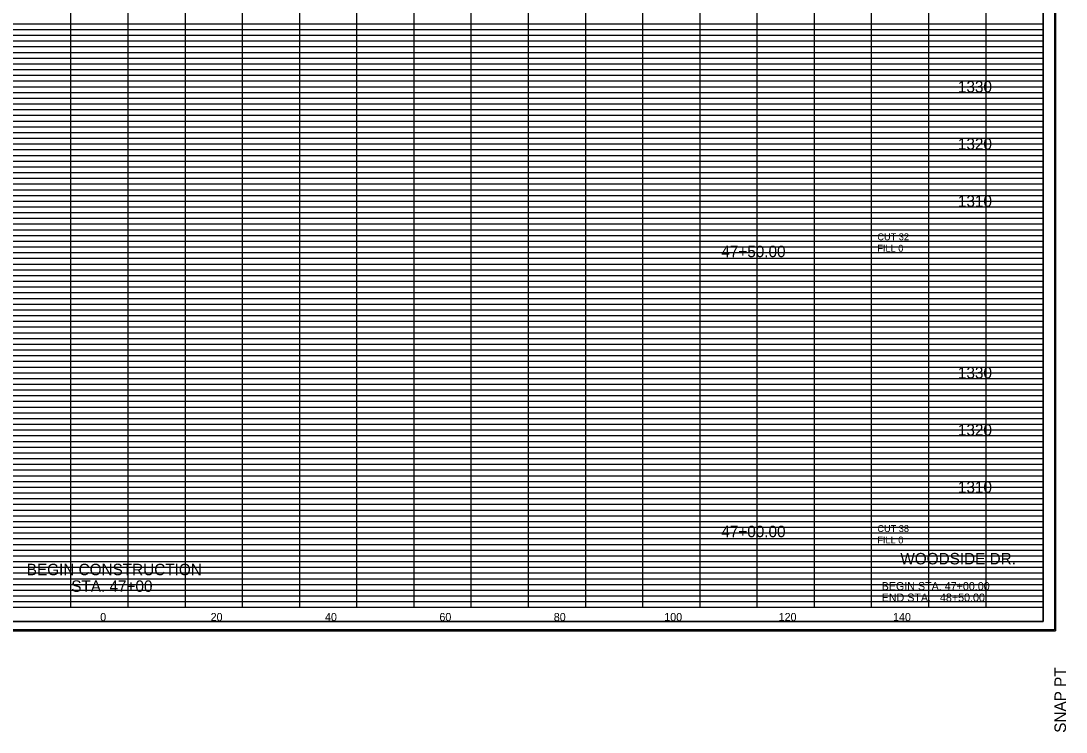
# Model space of a CAD drawing. Extents: x 980 to 1324, y 978 to 1497.
# Drawn here: x 1141.2 to 1324, y 978.2 to 1102.5 of the extents above; entities that cross this region are included whole.
import ezdxf

# ---------------------------------------------------------------- set-up
doc = ezdxf.new("R2010")
doc.units = 0
for name, color, linetype in [('DESIGN - SHEET - Corner Text', 7, 'Continuous'), ('DESIGN - SHEET - Light Grid', 7, 'Continuous'), ('DESIGN - SHEET - Linework', 7, 'Continuous'), ('DESIGN - SHEET - Plot Shape', 7, 'Continuous'), ('DESIGN - TYPICAL - Finished Grade and Subgrade', 7, 'Continuous'), ('DESIGN - TYPICAL - Text', 7, 'Continuous')]:
    doc.layers.add(name, color=color, linetype=linetype)

# ---------------------------------------------------------------- blocks, each defined once
blk = doc.blocks.new('XSTSHT')
at = {"layer": 'DESIGN - SHEET - Light Grid'}
for p, q in [((8, 10.2), (16, 10.2)), ((8, 10.1), (16, 10.1)), ((16, 10.2), (24, 10.2)), ((16, 10.1), (24, 10.1)), ((24, 10.2), (32, 10.2)), ((24, 10.1), (32, 10.1)), ((8, 9.9), (16, 9.9)), ((16, 9.9), (24, 9.9)), ((24, 9.9), (32, 9.9)), ((8, 9.8), (16, 9.8)), ((8, 9.7), (16, 9.7)), ((16, 9.8), (24, 9.8)), ((16, 9.7), (24, 9.7)), ((24, 9.8), (32, 9.8)), ((24, 9.7), (32, 9.7)), ((8, 9.6), (16, 9.6)), ((16, 9.6), (24, 9.6)), ((24, 9.6), (32, 9.6)), ((8, 9.5), (16, 9.5)), ((8, 9.4), (16, 9.4)), ((16, 9.5), (24, 9.5)), ((16, 9.4), (24, 9.4)), ((24, 9.5), (32, 9.5)), ((24, 9.4), (32, 9.4)), ((8, 9.3), (16, 9.3)), ((8, 9.2), (16, 9.2)), ((16, 9.3), (24, 9.3)), ((16, 9.2), (24, 9.2)), ((24, 9.3), (32, 9.3)), ((24, 9.2), (32, 9.2)), ((8, 9.1), (16, 9.1)), ((16, 9.1), (24, 9.1)), ((24, 9.1), (32, 9.1)), ((8, 8.9), (16, 8.9)), ((8, 8.8), (16, 8.8)), ((16, 8.9), (24, 8.9)), ((16, 8.8), (24, 8.8)), ((24, 8.9), (32, 8.9)), ((24, 8.8), (32, 8.8)), ((8, 8.7), (16, 8.7)), ((8, 8.6), (16, 8.6)), ((16, 8.7), (24, 8.7)), ((16, 8.6), (24, 8.6)), ((24, 8.7), (32, 8.7)), ((24, 8.6), (32, 8.6)), ((8, 8.5), (16, 8.5)), ((16, 8.5), (24, 8.5)), ((24, 8.5), (32, 8.5)), ((8, 8.4), (16, 8.4)), ((8, 8.3), (16, 8.3)), ((16, 8.4), (24, 8.4)), ((16, 8.3), (24, 8.3)), ((24, 8.4), (32, 8.4)), ((24, 8.3), (32, 8.3)), ((8, 8.2), (16, 8.2)), ((8, 8.1), (16, 8.1)), ((16, 8.2), (24, 8.2)), ((16, 8.1), (24, 8.1)), ((24, 8.2), (32, 8.2)), ((24, 8.1), (32, 8.1)), ((8, 7.9), (16, 7.9)), ((16, 7.9), (24, 7.9)), ((24, 7.9), (32, 7.9)), ((8, 7.8), (16, 7.8)), ((8, 7.7), (16, 7.7)), ((16, 7.8), (24, 7.8)), ((16, 7.7), (24, 7.7)), ((24, 7.8), (32, 7.8)), ((24, 7.7), (32, 7.7)), ((8, 7.6), (16, 7.6)), ((8, 7.5), (16, 7.5)), ((16, 7.6), (24, 7.6)), ((16, 7.5), (24, 7.5)), ((24, 7.6), (32, 7.6)), ((24, 7.5), (32, 7.5)), ((8, 7.4), (16, 7.4)), ((16, 7.4), (24, 7.4)), ((24, 7.4), (32, 7.4)), ((8, 7.3), (16, 7.3)), ((8, 7.2), (16, 7.2)), ((16, 7.3), (24, 7.3)), ((16, 7.2), (24, 7.2)), ((24, 7.3), (32, 7.3)), ((24, 7.2), (32, 7.2)), ((8, 7.1), (16, 7.1)), ((16, 7.1), (24, 7.1)), ((24, 7.1), (32, 7.1)), ((8, 6.9), (16, 6.9)), ((8, 6.8), (16, 6.8)), ((16, 6.9), (24, 6.9)), ((16, 6.8), (24, 6.8)), ((24, 6.9), (32, 6.9)), ((24, 6.8), (32, 6.8)), ((8, 6.7), (16, 6.7)), ((8, 6.6), (16, 6.6)), ((16, 6.7), (24, 6.7)), ((16, 6.6), (24, 6.6)), ((24, 6.7), (32, 6.7)), ((24, 6.6), (32, 6.6)), ((8, 6.5), (16, 6.5)), ((8, 6.4), (16, 6.4)), ((16, 6.5), (24, 6.5)), ((16, 6.4), (24, 6.4)), ((24, 6.5), (32, 6.5)), ((24, 6.4), (32, 6.4)), ((8, 6.3), (16, 6.3)), ((16, 6.3), (24, 6.3)), ((24, 6.3), (32, 6.3)), ((8, 6.2), (16, 6.2)), ((8, 6.1), (16, 6.1)), ((16, 6.2), (24, 6.2)), ((16, 6.1), (24, 6.1)), ((24, 6.2), (32, 6.2)), ((24, 6.1), (32, 6.1)), ((8, 5.9), (16, 5.9)), ((16, 5.9), (24, 5.9)), ((24, 5.9), (32, 5.9)), ((8, 5.8), (16, 5.8)), ((8, 5.7), (16, 5.7)), ((16, 5.8), (24, 5.8)), ((16, 5.7), (24, 5.7)), ((24, 5.8), (32, 5.8)), ((24, 5.7), (32, 5.7)), ((8, 5.6), (16, 5.6)), ((8, 5.5), (16, 5.5)), ((16, 5.6), (24, 5.6)), ((16, 5.5), (24, 5.5)), ((24, 5.6), (32, 5.6)), ((24, 5.5), (32, 5.5)), ((8, 5.4), (16, 5.4)), ((8, 5.3), (16, 5.3)), ((16, 5.4), (24, 5.4)), ((16, 5.3), (24, 5.3)), ((24, 5.4), (32, 5.4)), ((24, 5.3), (32, 5.3)), ((8, 5.2), (16, 5.2)), ((16, 5.2), (24, 5.2)), ((24, 5.2), (32, 5.2)), ((8, 5.1), (16, 5.1)), ((16, 5.1), (24, 5.1)), ((24, 5.1), (32, 5.1)), ((8, 4.9), (16, 4.9)), ((8, 4.8), (16, 4.8)), ((16, 4.9), (24, 4.9)), ((16, 4.8), (24, 4.8)), ((24, 4.9), (32, 4.9)), ((24, 4.8), (32, 4.8)), ((8, 4.7), (16, 4.7)), ((8, 4.6), (16, 4.6)), ((16, 4.7), (24, 4.7)), ((16, 4.6), (24, 4.6)), ((24, 4.7), (32, 4.7)), ((24, 4.6), (32, 4.6)), ((8, 4.5), (16, 4.5)), ((8, 4.4), (16, 4.4)), ((16, 4.5), (24, 4.5)), ((16, 4.4), (24, 4.4)), ((24, 4.5), (32, 4.5)), ((24, 4.4), (32, 4.4)), ((8, 4.3), (16, 4.3)), ((16, 4.3), (24, 4.3)), ((24, 4.3), (32, 4.3)), ((8, 4.2), (16, 4.2)), ((8, 4.1), (16, 4.1)), ((16, 4.2), (24, 4.2)), ((16, 4.1), (24, 4.1)), ((24, 4.2), (32, 4.2)), ((24, 4.1), (32, 4.1)), ((8, 3.9), (16, 3.9)), ((16, 3.9), (24, 3.9)), ((24, 3.9), (32, 3.9)), ((8, 3.8), (16, 3.8)), ((8, 3.7), (16, 3.7)), ((16, 3.8), (24, 3.8)), ((16, 3.7), (24, 3.7)), ((24, 3.8), (32, 3.8)), ((24, 3.7), (32, 3.7)), ((8, 3.6), (16, 3.6)), ((8, 3.5), (16, 3.5)), ((16, 3.6), (24, 3.6)), ((16, 3.5), (24, 3.5)), ((24, 3.6), (32, 3.6)), ((24, 3.5), (32, 3.5)), ((8, 3.4), (16, 3.4)), ((8, 3.3), (16, 3.3)), ((16, 3.4), (24, 3.4)), ((16, 3.3), (24, 3.3)), ((24, 3.4), (32, 3.4)), ((24, 3.3), (32, 3.3)), ((8, 3.2), (16, 3.2)), ((16, 3.2), (24, 3.2)), ((24, 3.2), (32, 3.2)), ((8, 3.1), (16, 3.1)), ((16, 3.1), (24, 3.1)), ((24, 3.1), (32, 3.1)), ((8, 2.9), (16, 2.9)), ((8, 2.8), (16, 2.8)), ((16, 2.9), (24, 2.9)), ((16, 2.8), (24, 2.8)), ((24, 2.9), (32, 2.9)), ((24, 2.8), (32, 2.8)), ((8, 2.7), (16, 2.7)), ((8, 2.6), (16, 2.6)), ((16, 2.7), (24, 2.7)), ((16, 2.6), (24, 2.6)), ((24, 2.7), (32, 2.7)), ((24, 2.6), (32, 2.6)), ((8, 2.5), (16, 2.5)), ((8, 2.4), (16, 2.4)), ((16, 2.5), (24, 2.5)), ((16, 2.4), (24, 2.4)), ((24, 2.5), (32, 2.5)), ((24, 2.4), (32, 2.4)), ((8, 2.3), (16, 2.3)), ((8, 2.2), (16, 2.2)), ((16, 2.3), (24, 2.3)), ((16, 2.2), (24, 2.2)), ((24, 2.3), (32, 2.3)), ((24, 2.2), (32, 2.2)), ((8, 2.1), (16, 2.1)), ((16, 2.1), (24, 2.1)), ((24, 2.1), (32, 2.1)), ((8, 1.9), (16, 1.9)), ((16, 1.9), (24, 1.9)), ((24, 1.9), (32, 1.9)), ((8, 1.8), (16, 1.8)), ((8, 1.7), (16, 1.7)), ((16, 1.8), (24, 1.8)), ((16, 1.7), (24, 1.7)), ((24, 1.8), (32, 1.8)), ((24, 1.7), (32, 1.7)), ((8, 1.6), (16, 1.6)), ((8, 1.5), (16, 1.5)), ((16, 1.6), (24, 1.6)), ((16, 1.5), (24, 1.5)), ((24, 1.6), (32, 1.6)), ((24, 1.5), (32, 1.5)), ((8, 1.4), (16, 1.4)), ((8, 1.3), (16, 1.3)), ((16, 1.4), (24, 1.4)), ((16, 1.3), (24, 1.3)), ((24, 1.4), (32, 1.4)), ((24, 1.3), (32, 1.3)), ((8, 1.2), (16, 1.2)), ((8, 1.1), (16, 1.1)), ((16, 1.2), (24, 1.2)), ((16, 1.1), (24, 1.1)), ((24, 1.2), (32, 1.2)), ((24, 1.1), (32, 1.1)), ((8, 0.9), (16, 0.9)), ((8, 0.8), (16, 0.8)), ((16, 0.9), (24, 0.9)), ((16, 0.8), (24, 0.8)), ((24, 0.9), (32, 0.9)), ((24, 0.8), (32, 0.8)), ((8, 0.7), (16, 0.7)), ((8, 0.6), (16, 0.6)), ((16, 0.7), (24, 0.7)), ((16, 0.6), (24, 0.6)), ((24, 0.7), (32, 0.7)), ((24, 0.6), (32, 0.6)), ((8, 0.5), (16, 0.5)), ((8, 0.4), (16, 0.4)), ((16, 0.5), (24, 0.5)), ((16, 0.4), (24, 0.4)), ((24, 0.5), (32, 0.5)), ((24, 0.4), (32, 0.4)), ((8, 0.3), (16, 0.3)), ((8, 0.2), (16, 0.2)), ((16, 0.3), (24, 0.3)), ((16, 0.2), (24, 0.2)), ((24, 0.3), (32, 0.3)), ((24, 0.2), (32, 0.2)), ((8, 0.1), (16, 0.1)), ((16, 0.1), (24, 0.1)), ((24, 0.1), (32, 0.1))]:
    blk.add_line(p, q, dxfattribs=at)
at = {"layer": 'DESIGN - SHEET - Linework'}
for p, q in [((32.217, 21.414), (32.217, -0.414)), ((15, 0), (15, 21)), ((16, 0), (16, 21)), ((17, 0), (17, 21)), ((18, 0), (18, 21)), ((19, 0), (19, 21)), ((20, 0), (20, 21)), ((21, 0), (21, 21)), ((22, 0), (22, 21)), ((23, 0), (23, 21)), ((24, 0), (24, 21)), ((25, 0), (25, 21)), ((26, 0), (26, 21)), ((27, 0), (27, 21)), ((28, 0), (28, 20)), ((29, 0), (29, 20)), ((30, 0), (30, 20)), ((31, 0), (31, 20)), ((0, 10), (32, 10)), ((0, 9), (32, 9)), ((0, 8), (32, 8)), ((0, 7), (32, 7)), ((0, 6), (32, 6)), ((0, 5), (32, 5)), ((0, 4), (32, 4)), ((0, 3), (32, 3)), ((0, 2), (32, 2)), ((0, 1), (32, 1)), ((-1.823, -0.414), (32.217, -0.414))]:
    blk.add_line(p, q, dxfattribs=at)
blk.add_lwpolyline([(0, 21), (0, 0), (32, 0), (32, 21), (0, 21)], dxfattribs=at)
at = {"layer": 'DESIGN - SHEET - Plot Shape'}
for points in [[(-1.803, 21.394), (32.197, 21.394), (32.197, -0.394), (-1.803, -0.394)], [(-0.85, 21), (32, 21), (32, -0.25), (-0.85, -0.25)]]:
    blk.add_lwpolyline(points, close=True, dxfattribs=at)
at = {"layer": 'DESIGN - SHEET - Corner Text'}
blk.add_text('SNAP PT  ', height=0.2, rotation=90, dxfattribs=at).set_placement((32.397, -2.194))

msp = doc.modelspace()

# ---------------------------------------------------------------- linework, layer by layer
at = {"layer": 'DESIGN - SHEET - Plot Shape'}
msp.add_lwpolyline([(991.5, 997.5), (1320, 997.5), (1320, 1210), (991.5, 1210)], close=True, dxfattribs=at)

# ---------------------------------------------------------------- block references
at = {"layer": 'DESIGN - TYPICAL - Finished Grade and Subgrade', "xscale": 10, "yscale": 10}
msp.add_blockref('XSTSHT', (1000, 1000), dxfattribs=at)

# ---------------------------------------------------------------- texts
at = {"layer": 'DESIGN - SHEET - Corner Text'}
for s, height, p in [('WOODSIDE DR.', 2, (1295.02, 1007.5)), ('BEGIN STA. 47+00.00', 1.4, (1291.75, 1003)), ('END STA.   48+50.00', 1.4, (1291.75, 1001))]:
    msp.add_text(s, height=height, dxfattribs=at).set_placement(p)
at = {"layer": 'DESIGN - TYPICAL - Text'}
for s, height, p in [('     1330     ', 2, (1301.37, 1090)), ('     1320     ', 2, (1301.37, 1080)), ('     1310     ', 2, (1301.37, 1070)), ('CUT 32', 1.2, (1291, 1064.16)), ('     47+50.00     ', 2, (1260, 1061.2)), ('FILL 0', 1.2, (1291, 1062.16)), ('     1330     ', 2, (1301.37, 1040)), ('     1320     ', 2, (1301.37, 1030)), ('     1310     ', 2, (1301.37, 1020)), ('     47+00.00     ', 2, (1260, 1012.25)), ('CUT 38', 1.2, (1291, 1013.16)), ('FILL 0', 1.2, (1291, 1011.16)), ('BEGIN CONSTRUCTION', 2, (1142.27, 1005.6)), ('STA. 47+00', 2, (1150.05, 1002.7)), ('     0     ', 1.4, (1152.51, 997.6)), ('     0     ', 1.4, (1152.51, 997.6)), ('     20     ', 1.4, (1171.82, 997.6)), ('     40     ', 1.4, (1191.82, 997.6)), ('     60     ', 1.4, (1211.82, 997.6)), ('     80     ', 1.4, (1231.82, 997.6)), ('     100     ', 1.4, (1251.14, 997.6)), ('     120     ', 1.4, (1271.14, 997.6)), ('     140     ', 1.4, (1291.14, 997.6))]:
    msp.add_text(s, height=height, dxfattribs=at).set_placement(p)

doc.saveas('drawing.dxf')
